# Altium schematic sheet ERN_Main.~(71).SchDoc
size A; SheetNumber: 1; SheetTotal: 4; SPICEModelCacheDBTNACQE: <root> / <DocumentId>DBTNACQE</DocumentId> / </root>
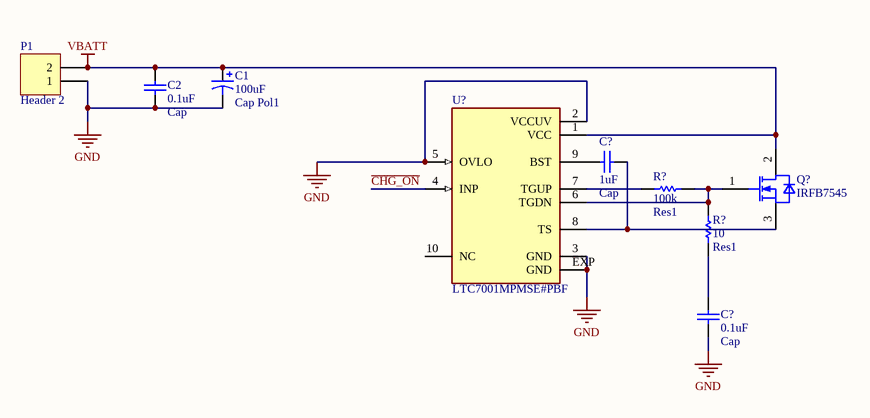
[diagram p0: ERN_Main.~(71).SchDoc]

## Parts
(Parts that share a designator on the sheet are numbered #1, #2 ... from top to bottom, then left to right.)
C1  Cap Pol1  value 100uF  [RB7.6-15]
C2  Cap  value 0.1uF  [RAD-0.3]
C?#1  Cap  value 1uF  [RAD-0.3]
C?#2  Cap  value 0.1uF  [RAD-0.3]
P1  Header 2  [HDR1X2]
Q?  IRFB7545  [IFX-PG-TO220-3-904]
R?#1  Res1  value 100k  [AXIAL-0.3]
R?#2  Res1  value 10  [AXIAL-0.3]
U?  LTC7001MPMSE#PBF  [SOP50P490X110-11N]

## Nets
GND: C1.2 C2.1 C?#2.2 P1.1 U?.2(VCCUV) U?.3(GND) U?.5(OVLO) U?.EXP(GND)
VBATT: C1.1 C2.2 P1.2 Q?.2(DRAIN) U?.1(VCC)
~{CHG_ON}: U?.4(INP)
NetC?#1_1: C?#1.1 Q?.3(SOURCE) U?.8(TS)
NetC?#1_2: C?#1.2 U?.9(BST)
NetC?#2_1: C?#2.1 R?#2.2
NetQ?_1: Q?.1(GATE) R?#1.1 R?#2.1 U?.6(TGDN)
NetR?#1_2: R?#1.2 U?.7(TGUP)

Not connected (* = marked no-connect by the designer): U? 10(NC)

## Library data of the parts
C1 = Cap Pol1: Polarized Capacitor (Radial)
C2 C?#1 C?#2 = Cap: Capacitor
P1 = Header 2: Header, 2-Pin
Q? = IRFB7545: N-Channel 60V 95A; Insulated-Gate Field-Effect Transistor (IGFET), N-Channel, Enhancement, Body Diode, Pin 1 Gate, 2 Drain, 3 Source, 3 Pins; Manufacturer: Infineon Technologies
R?#1 R?#2 = Res1: Resistor
U? = LTC7001MPMSE#PBF: Fast 150V High Side NMOS Static Switch Driver; MF: Analog Devices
